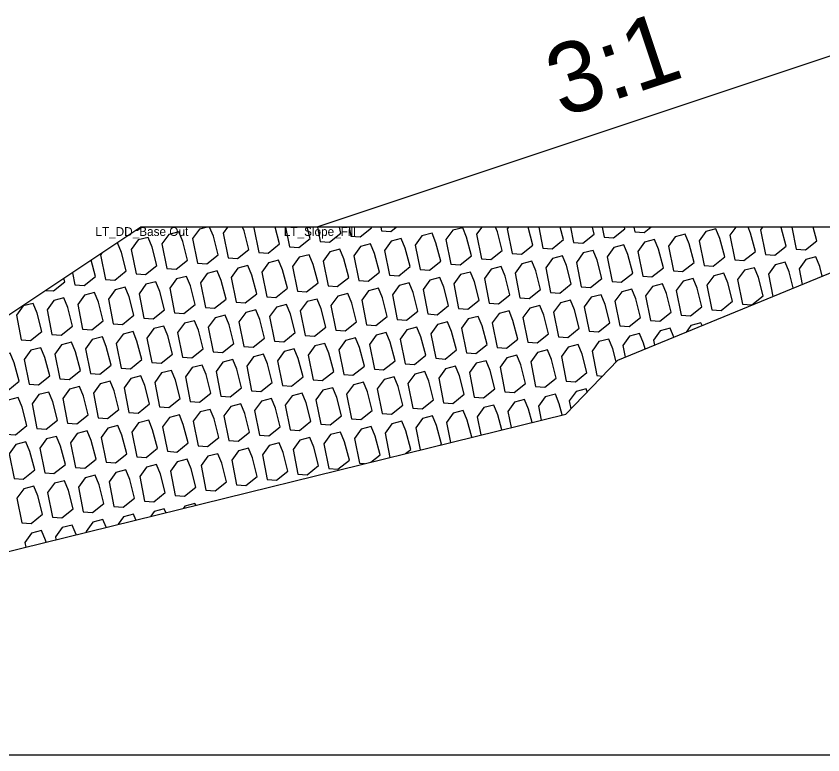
# Model space of a CAD drawing. Extents: x -26 to 203, y -10 to 20020.
# Drawn here: x 69.63 to 78.79, y 3000 to 3008.4 of the extents above; entities that cross this region are included whole.
import ezdxf

# ---------------------------------------------------------------- set-up
doc = ezdxf.new("R2010")
doc.units = 0
for name, color, linetype in [('Default', 7, 'Continuous'), ('Exist Cross Section Cell', 7, 'Continuous'), ('Exist XS Ground Line', 7, 'Continuous'), ('Old_Level_1', 7, 'Continuous'), ('Prop CMT Rip Rap Class II', 7, 'Continuous'), ('Prop CMT Slope Grass', 7, 'Continuous'), ('Prop XS Side Slope Text', 7, 'Continuous')]:
    doc.layers.add(name, color=color, linetype=linetype)

msp = doc.modelspace()

# ---------------------------------------------------------------- linework, layer by layer
at = {"layer": 'Exist Cross Section Cell'}
msp.add_line((0, 3000), (100, 3000), dxfattribs=at)
at = {"layer": 'Exist XS Ground Line'}
for p, q in [((76.4636, 3004.4871), (83.4343, 3007.3577)), ((75.8737, 3003.8749), (76.4636, 3004.4871)), ((69.1249, 3002.2125), (75.8737, 3003.8749))]:
    msp.add_line(p, q, dxfattribs=at)
at = {"layer": 'Old_Level_1'}
for p, q in [((72.69, 3006), (72.7347, 3005.7748)), ((73.0508, 3006), (73.0833, 3005.8363)), ((73.4116, 3006), (73.4319, 3005.8977)), ((73.7724, 3006), (73.7805, 3005.9592)), ((75.5652, 3006), (75.6123, 3005.7625)), ((75.926, 3006), (75.9609, 3005.8239)), ((76.2868, 3006), (76.3095, 3005.8854)), ((76.6476, 3006), (76.6581, 3005.9469)), ((78.4404, 3006), (78.49, 3005.7501)), ((70.2673, 3005.4814), (70.2945, 3005.3445)), ((76.2276, 3004.3117), (76.2903, 3004.3072)), ((73.5277, 3003.3159), (73.5869, 3003.3116))]:
    msp.add_line(p, q, dxfattribs=at)
for points in [[(70.9927, 3005.965), (71.0081, 3005.9639), (71.0534, 3006)], [(71.8, 3006), (71.7104, 3005.9768), (71.6333, 3005.8704), (71.6889, 3005.5904)], [(71.6889, 3005.5904), (71.7942, 3005.5828), (71.9237, 3005.686), (71.8693, 3005.8965), (71.8267, 3006)], [(72.0312, 3006), (71.9819, 3005.9319), (72.0375, 3005.6519)], [(72.0375, 3005.6519), (72.1428, 3005.6442), (72.2723, 3005.7474), (72.2179, 3005.958), (72.2006, 3006)], [(72.3353, 3006), (72.3305, 3005.9933), (72.3861, 3005.7133)], [(72.3861, 3005.7133), (72.4914, 3005.7057), (72.6209, 3005.8089), (72.5715, 3006)], [(72.7347, 3005.7748), (72.84, 3005.7672), (72.9695, 3005.8704), (72.936, 3006)], [(73.0833, 3005.8363), (73.1886, 3005.8286), (73.3181, 3005.9318), (73.3005, 3006)], [(73.4319, 3005.8977), (73.5372, 3005.8901), (73.6667, 3005.9933), (73.665, 3006)], [(73.7805, 3005.9592), (73.8857, 3005.9516), (73.9465, 3006)], [(74.9178, 3006), (74.8595, 3005.9195), (74.9152, 3005.6395)], [(74.9152, 3005.6395), (75.0204, 3005.6319), (75.15, 3005.7351), (75.0955, 3005.9457), (75.0732, 3006)], [(75.2219, 3006), (75.2081, 3005.981), (75.2638, 3005.701)], [(75.2638, 3005.701), (75.369, 3005.6934), (75.4986, 3005.7966), (75.446, 3006)], [(75.6123, 3005.7625), (75.7176, 3005.7548), (75.8472, 3005.858), (75.8104, 3006)], [(75.9609, 3005.8239), (76.0662, 3005.8163), (76.1957, 3005.9195), (76.1749, 3006)], [(76.3095, 3005.8854), (76.4148, 3005.8778), (76.5443, 3005.981), (76.5394, 3006)], [(76.6581, 3005.9469), (76.7634, 3005.9392), (76.8397, 3006)], [(77.4442, 3005.5657), (77.5495, 3005.5581), (77.679, 3005.6613), (77.6246, 3005.8719), (77.5794, 3005.9816), (77.4657, 3005.9522), (77.3886, 3005.8457), (77.4442, 3005.5657)], [(77.8044, 3006), (77.7372, 3005.9072), (77.7928, 3005.6272)], [(77.7928, 3005.6272), (77.8981, 3005.6196), (78.0276, 3005.7228), (77.9732, 3005.9333), (77.9457, 3006)], [(78.1085, 3006), (78.0858, 3005.9687), (78.1414, 3005.6887)], [(78.1414, 3005.6887), (78.2467, 3005.681), (78.3762, 3005.7842), (78.3218, 3005.9948), (78.3196, 3006)], [(78.49, 3005.7501), (78.5953, 3005.7425), (78.7248, 3005.8457), (78.6849, 3006)], [(70.6431, 3005.406), (70.7484, 3005.3984), (70.8779, 3005.5016), (70.8235, 3005.7121), (70.7783, 3005.8218), (70.7777, 3005.8217)], [(73.5208, 3005.3937), (73.626, 3005.386), (73.7556, 3005.4892), (73.7011, 3005.6998), (73.656, 3005.8095), (73.5422, 3005.7801), (73.4652, 3005.6737), (73.5208, 3005.3937)], [(73.8694, 3005.4551), (73.9746, 3005.4475), (74.1042, 3005.5507), (74.0497, 3005.7613), (74.0046, 3005.871), (73.8908, 3005.8416), (73.8138, 3005.7351), (73.8694, 3005.4551)], [(70.2945, 3005.3445), (70.3998, 3005.3369), (70.5293, 3005.4401), (70.4817, 3005.6243)], [(70.5999, 3005.7031), (70.5875, 3005.686), (70.6431, 3005.406)], [(78.7872, 3005.444), (78.7592, 3005.5522), (78.7141, 3005.6619), (78.6003, 3005.6325), (78.5233, 3005.5261), (78.5583, 3005.3497)], [(78.4578, 3005.3083), (78.4106, 3005.4907), (78.3655, 3005.6004), (78.2517, 3005.571), (78.1747, 3005.4646), (78.2248, 3005.2123)], [(74.6554, 3005.074), (74.7607, 3005.0664), (74.8902, 3005.1696), (74.8358, 3005.3801), (74.7907, 3005.4898), (74.6769, 3005.4604), (74.5998, 3005.354), (74.6554, 3005.074)], [(69.9675, 3005.2815), (70.0512, 3005.2754), (70.1807, 3005.3786), (70.1708, 3005.417)], [(74.3068, 3005.0125), (74.4121, 3005.0049), (74.5416, 3005.1081), (74.4872, 3005.3187), (74.4421, 3005.4284), (74.3283, 3005.399), (74.2512, 3005.2925), (74.3068, 3005.0125)], [(76.8359, 3004.9387), (76.9412, 3004.9311), (77.0707, 3005.0343), (77.0163, 3005.2449), (76.9711, 3005.3546), (76.8574, 3005.3252), (76.7803, 3005.2187), (76.8359, 3004.9387)], [(77.1845, 3005.0002), (77.2898, 3004.9926), (77.4193, 3005.0958), (77.3649, 3005.3063), (77.3197, 3005.416), (77.2059, 3005.3866), (77.1289, 3005.2802), (77.1845, 3005.0002)], [(75.7901, 3004.7543), (75.8954, 3004.7467), (76.0249, 3004.8499), (75.9705, 3005.0605), (75.9253, 3005.1702), (75.8116, 3005.1408), (75.7345, 3005.0343), (75.7901, 3004.7543)], [(75.4415, 3004.6929), (75.5468, 3004.6852), (75.6763, 3004.7884), (75.6219, 3004.999), (75.5767, 3005.1087), (75.463, 3005.0793), (75.3859, 3004.9729), (75.4415, 3004.6929)], [(75.0929, 3004.6314), (75.1982, 3004.6238), (75.3277, 3004.727), (75.2733, 3004.9375), (75.2281, 3005.0472), (75.1144, 3005.0178), (75.0373, 3004.9114), (75.0929, 3004.6314)], [(77.4212, 3004.8814), (77.4086, 3004.912), (77.2948, 3004.8826), (77.24, 3004.8068)], [(76.7733, 3004.6146), (76.7565, 3004.6793), (76.7114, 3004.789), (76.5976, 3004.7596), (76.5206, 3004.6532), (76.5468, 3004.5213)], [(77.1015, 3004.7497), (77.06, 3004.8505), (76.9462, 3004.8211), (76.8692, 3004.7147), (76.8803, 3004.6587)], [(76.4464, 3004.4692), (76.4079, 3004.6179), (76.3628, 3004.7276), (76.249, 3004.6982), (76.172, 3004.5917), (76.2276, 3004.3117)], [(75.879, 3004.2503), (75.9843, 3004.2426), (76.1138, 3004.3458), (76.0593, 3004.5564), (76.0142, 3004.6661), (75.9004, 3004.6367), (75.8234, 3004.5303), (75.879, 3004.2503)], [(76.1172, 3004.1276), (76.1031, 3004.162), (75.9893, 3004.1326), (75.9123, 3004.0262), (75.9306, 3003.9339)], [(75.8322, 3003.8647), (75.7996, 3003.9909), (75.7545, 3004.1006), (75.6407, 3004.0711), (75.5637, 3003.9647), (75.5951, 3003.8063)], [(75.1469, 3003.6959), (75.1024, 3003.8679), (75.0573, 3003.9776), (74.9435, 3003.9482), (74.8665, 3003.8418), (74.9072, 3003.6368)], [(75.4896, 3003.7803), (75.451, 3003.9294), (75.4059, 3004.0391), (75.2921, 3004.0097), (75.2151, 3003.9033), (75.2512, 3003.7216)], [(74.8043, 3003.6115), (74.7538, 3003.8065), (74.7087, 3003.9162), (74.5949, 3003.8867), (74.5179, 3003.7803), (74.5632, 3003.5521)], [(74.0526, 3003.4263), (74.1111, 3003.473), (74.0566, 3003.6835), (74.0115, 3003.7932), (73.8977, 3003.7638), (73.8207, 3003.6574), (73.8752, 3003.3826)], [(74.4455, 3003.5231), (74.4597, 3003.5344), (74.4052, 3003.745), (74.3601, 3003.8547), (74.2463, 3003.8253), (74.1693, 3003.7189), (74.2192, 3003.4674)], [(73.6596, 3003.3295), (73.7625, 3003.4115), (73.7081, 3003.6221), (73.6629, 3003.7318), (73.5491, 3003.7023), (73.4721, 3003.5959), (73.5277, 3003.3159)], [(71.3289, 3002.7554), (71.3116, 3002.7974), (71.1979, 3002.768), (71.1583, 3002.7134)], [(71.6684, 3002.839), (71.6602, 3002.8589), (71.5464, 3002.8295), (71.5284, 3002.8046)], [(70.9894, 3002.6718), (70.963, 3002.736), (70.8493, 3002.7065), (70.7882, 3002.6222)], [(70.3105, 3002.5045), (70.2658, 3002.613), (70.1521, 3002.5836), (70.075, 3002.4772), (70.0808, 3002.448)], [(70.6499, 3002.5882), (70.6144, 3002.6745), (70.5007, 3002.6451), (70.4236, 3002.5386), (70.4248, 3002.5327)], [(69.968, 3002.4202), (69.9624, 3002.4419), (69.9172, 3002.5516), (69.8035, 3002.5221), (69.7264, 3002.4157), (69.7368, 3002.3632)]]:
    msp.add_lwpolyline(points, dxfattribs=at)
for points in [[(74.5666, 3005.5781), (74.6718, 3005.5704), (74.8014, 3005.6736), (74.7469, 3005.8842), (74.7018, 3005.9939), (74.588, 3005.9645), (74.5109, 3005.8581)], [(71.3403, 3005.5289), (71.4456, 3005.5213), (71.5751, 3005.6245), (71.5207, 3005.8351), (71.4755, 3005.9448), (71.3618, 3005.9154), (71.2847, 3005.8089)], [(74.218, 3005.5166), (74.3232, 3005.509), (74.4528, 3005.6122), (74.3983, 3005.8227), (74.3532, 3005.9324), (74.2394, 3005.903), (74.1624, 3005.7966)], [(77.0956, 3005.5043), (77.2009, 3005.4966), (77.3304, 3005.5998), (77.276, 3005.8104), (77.2308, 3005.9201), (77.1171, 3005.8907), (77.04, 3005.7843)], [(70.9917, 3005.4675), (71.097, 3005.4598), (71.2265, 3005.563), (71.1721, 3005.7736), (71.1269, 3005.8833), (71.0132, 3005.8539), (70.9361, 3005.7475)], [(76.3984, 3005.3813), (76.5037, 3005.3737), (76.6332, 3005.4769), (76.5788, 3005.6875), (76.5336, 3005.7972), (76.4199, 3005.7678), (76.3428, 3005.6613)], [(76.747, 3005.4428), (76.8523, 3005.4352), (76.9818, 3005.5384), (76.9274, 3005.7489), (76.8822, 3005.8586), (76.7685, 3005.8292), (76.6914, 3005.7228)], [(73.1722, 3005.3322), (73.2774, 3005.3246), (73.407, 3005.4278), (73.3525, 3005.6383), (73.3074, 3005.748), (73.1936, 3005.7186), (73.1166, 3005.6122)], [(76.0498, 3005.3199), (76.1551, 3005.3122), (76.2846, 3005.4154), (76.2302, 3005.626), (76.185, 3005.7357), (76.0713, 3005.7063), (75.9942, 3005.5999)], [(72.475, 3005.2093), (72.5802, 3005.2016), (72.7098, 3005.3048), (72.6553, 3005.5154), (72.6102, 3005.6251), (72.4964, 3005.5957), (72.4194, 3005.4893)], [(72.8236, 3005.2707), (72.9288, 3005.2631), (73.0584, 3005.3663), (73.0039, 3005.5769), (72.9588, 3005.6866), (72.845, 3005.6572), (72.768, 3005.5507)], [(75.7012, 3005.2584), (75.8065, 3005.2508), (75.936, 3005.354), (75.8816, 3005.5645), (75.8364, 3005.6742), (75.7227, 3005.6448), (75.6456, 3005.5384)], [(72.1264, 3005.1478), (72.2316, 3005.1402), (72.3612, 3005.2434), (72.3067, 3005.4539), (72.2616, 3005.5636), (72.1478, 3005.5342), (72.0708, 3005.4278)], [(75.004, 3005.1355), (75.1093, 3005.1278), (75.2388, 3005.231), (75.1844, 3005.4416), (75.1392, 3005.5513), (75.0255, 3005.5219), (74.9484, 3005.4155)], [(75.3526, 3005.1969), (75.4579, 3005.1893), (75.5874, 3005.2925), (75.533, 3005.5031), (75.4878, 3005.6128), (75.3741, 3005.5834), (75.297, 3005.4769)], [(77.8817, 3005.1231), (77.987, 3005.1155), (78.1165, 3005.2187), (78.062, 3005.4293), (78.0169, 3005.539), (77.9031, 3005.5096), (77.8261, 3005.4031)], [(71.4292, 3005.0249), (71.5345, 3005.0172), (71.664, 3005.1204), (71.6095, 3005.331), (71.5644, 3005.4407), (71.4506, 3005.4113), (71.3736, 3005.3049)], [(71.7778, 3005.0863), (71.883, 3005.0787), (72.0126, 3005.1819), (71.9581, 3005.3925), (71.913, 3005.5022), (71.7992, 3005.4728), (71.7222, 3005.3663)], [(77.5331, 3005.0617), (77.6384, 3005.054), (77.7679, 3005.1572), (77.7135, 3005.3678), (77.6683, 3005.4775), (77.5545, 3005.4481), (77.4775, 3005.3417)], [(71.0806, 3004.9634), (71.1859, 3004.9558), (71.3154, 3005.059), (71.2609, 3005.2695), (71.2158, 3005.3792), (71.102, 3005.3498), (71.025, 3005.2434)], [(73.9582, 3004.9511), (74.0635, 3004.9434), (74.193, 3005.0466), (74.1386, 3005.2572), (74.0935, 3005.3669), (73.9797, 3005.3375), (73.9026, 3005.2311)], [(70.3834, 3004.8405), (70.4887, 3004.8328), (70.6182, 3004.936), (70.5638, 3005.1466), (70.5186, 3005.2563), (70.4049, 3005.2269), (70.3278, 3005.1205)], [(70.732, 3004.9019), (70.8373, 3004.8943), (70.9668, 3004.9975), (70.9124, 3005.2081), (70.8672, 3005.3178), (70.7534, 3005.2884), (70.6764, 3005.1819)], [(73.6096, 3004.8896), (73.7149, 3004.882), (73.8445, 3004.9852), (73.79, 3005.1957), (73.7449, 3005.3054), (73.6311, 3005.276), (73.554, 3005.1696)], [(76.4873, 3004.8773), (76.5926, 3004.8696), (76.7221, 3004.9728), (76.6677, 3005.1834), (76.6225, 3005.2931), (76.5088, 3005.2637), (76.4317, 3005.1573)], [(70.0348, 3004.779), (70.1401, 3004.7714), (70.2696, 3004.8746), (70.2152, 3005.0851), (70.17, 3005.1948), (70.0563, 3005.1654), (69.9792, 3005.059)], [(72.9125, 3004.7667), (73.0177, 3004.759), (73.1473, 3004.8622), (73.0928, 3005.0728), (73.0477, 3005.1825), (72.9339, 3005.1531), (72.8568, 3005.0467)], [(73.2611, 3004.8281), (73.3663, 3004.8205), (73.4959, 3004.9237), (73.4414, 3005.1343), (73.3963, 3005.244), (73.2825, 3005.2146), (73.2054, 3005.1081)], [(76.1387, 3004.8158), (76.244, 3004.8082), (76.3735, 3004.9114), (76.3191, 3005.1219), (76.2739, 3005.2316), (76.1602, 3005.2022), (76.0831, 3005.0958)], [(69.6862, 3004.7175), (69.7915, 3004.7099), (69.921, 3004.8131), (69.8666, 3005.0237), (69.8214, 3005.1334), (69.7077, 3005.104), (69.6306, 3004.9975)], [(72.5639, 3004.7052), (72.6691, 3004.6976), (72.7987, 3004.8008), (72.7442, 3005.0113), (72.6991, 3005.121), (72.5853, 3005.0916), (72.5083, 3004.9852)], [(71.8667, 3004.5823), (71.9719, 3004.5746), (72.1015, 3004.6778), (72.047, 3004.8884), (72.0019, 3004.9981), (71.8881, 3004.9687), (71.8111, 3004.8623)], [(72.2153, 3004.6437), (72.3205, 3004.6361), (72.4501, 3004.7393), (72.3956, 3004.9499), (72.3505, 3005.0596), (72.2367, 3005.0302), (72.1597, 3004.9237)], [(74.7443, 3004.5699), (74.8496, 3004.5623), (74.9791, 3004.6655), (74.9247, 3004.8761), (74.8795, 3004.9858), (74.7658, 3004.9564), (74.6887, 3004.8499)], [(71.5181, 3004.5208), (71.6233, 3004.5132), (71.7529, 3004.6164), (71.6984, 3004.8269), (71.6533, 3004.9366), (71.5395, 3004.9072), (71.4625, 3004.8008)], [(74.3957, 3004.5085), (74.501, 3004.5008), (74.6305, 3004.604), (74.5761, 3004.8146), (74.5309, 3004.9243), (74.4172, 3004.8949), (74.3401, 3004.7885)], [(70.8209, 3004.3979), (70.9261, 3004.3902), (71.0557, 3004.4934), (71.0012, 3004.704), (70.9561, 3004.8137), (70.8423, 3004.7843), (70.7653, 3004.6779)], [(71.1695, 3004.4593), (71.2747, 3004.4517), (71.4043, 3004.5549), (71.3498, 3004.7655), (71.3047, 3004.8752), (71.1909, 3004.8458), (71.1139, 3004.7393)], [(73.6985, 3004.3855), (73.8038, 3004.3779), (73.9333, 3004.4811), (73.8789, 3004.6917), (73.8337, 3004.8014), (73.72, 3004.772), (73.6429, 3004.6655)], [(74.0471, 3004.447), (74.1524, 3004.4394), (74.2819, 3004.5426), (74.2275, 3004.7531), (74.1823, 3004.8628), (74.0686, 3004.8334), (73.9915, 3004.727)], [(70.4723, 3004.3364), (70.5775, 3004.3288), (70.7071, 3004.432), (70.6526, 3004.6425), (70.6075, 3004.7522), (70.4937, 3004.7228), (70.4167, 3004.6164)], [(73.3499, 3004.3241), (73.4552, 3004.3164), (73.5847, 3004.4196), (73.5303, 3004.6302), (73.4851, 3004.7399), (73.3714, 3004.7105), (73.2943, 3004.6041)], [(69.7751, 3004.2135), (69.8804, 3004.2058), (70.0099, 3004.309), (69.9554, 3004.5196), (69.9103, 3004.6293), (69.7965, 3004.5999), (69.7195, 3004.4935)], [(70.1237, 3004.2749), (70.2289, 3004.2673), (70.3585, 3004.3705), (70.304, 3004.5811), (70.2589, 3004.6908), (70.1451, 3004.6614), (70.0681, 3004.5549)], [(72.6527, 3004.2011), (72.758, 3004.1935), (72.8875, 3004.2967), (72.8331, 3004.5073), (72.788, 3004.617), (72.6742, 3004.5876), (72.5971, 3004.4811)], [(73.0013, 3004.2626), (73.1066, 3004.255), (73.2361, 3004.3582), (73.1817, 3004.5687), (73.1365, 3004.6784), (73.0228, 3004.649), (72.9457, 3004.5426)], [(69.4265, 3004.152), (69.5318, 3004.1444), (69.6613, 3004.2476), (69.6068, 3004.4581), (69.5617, 3004.5678), (69.4479, 3004.5384), (69.3709, 3004.432)], [(72.3041, 3004.1397), (72.4094, 3004.132), (72.5389, 3004.2352), (72.4845, 3004.4458), (72.4394, 3004.5555), (72.3256, 3004.5261), (72.2485, 3004.4197)], [(75.1818, 3004.1273), (75.2871, 3004.1197), (75.4166, 3004.2229), (75.3622, 3004.4335), (75.317, 3004.5432), (75.2033, 3004.5138), (75.1262, 3004.4073)], [(75.5304, 3004.1888), (75.6357, 3004.1812), (75.7652, 3004.2844), (75.7108, 3004.4949), (75.6656, 3004.6046), (75.5518, 3004.5752), (75.4748, 3004.4688)], [(71.607, 3004.0167), (71.7122, 3004.0091), (71.8418, 3004.1123), (71.7873, 3004.3229), (71.7422, 3004.4326), (71.6284, 3004.4031), (71.5513, 3004.2967)], [(71.9555, 3004.0782), (72.0608, 3004.0706), (72.1903, 3004.1738), (72.1359, 3004.3843), (72.0908, 3004.494), (71.977, 3004.4646), (71.8999, 3004.3582)], [(74.8332, 3004.0659), (74.9385, 3004.0582), (75.068, 3004.1614), (75.0136, 3004.372), (74.9684, 3004.4817), (74.8547, 3004.4523), (74.7776, 3004.3459)], [(71.2584, 3003.9553), (71.3636, 3003.9476), (71.4932, 3004.0508), (71.4387, 3004.2614), (71.3936, 3004.3711), (71.2798, 3004.3417), (71.2027, 3004.2353)], [(74.136, 3003.9429), (74.2413, 3003.9353), (74.3708, 3004.0385), (74.3164, 3004.2491), (74.2712, 3004.3588), (74.1575, 3004.3293), (74.0804, 3004.2229)], [(74.4846, 3004.0044), (74.5899, 3003.9968), (74.7194, 3004.1), (74.665, 3004.3105), (74.6198, 3004.4202), (74.5061, 3004.3908), (74.429, 3004.2844)], [(70.5612, 3003.8323), (70.6664, 3003.8247), (70.796, 3003.9279), (70.7415, 3004.1385), (70.6964, 3004.2482), (70.5826, 3004.2187), (70.5056, 3004.1123)], [(70.9098, 3003.8938), (71.015, 3003.8861), (71.1446, 3003.9894), (71.0901, 3004.1999), (71.045, 3004.3096), (70.9312, 3004.2802), (70.8541, 3004.1738)], [(73.7874, 3003.8815), (73.8927, 3003.8738), (74.0222, 3003.977), (73.9678, 3004.1876), (73.9226, 3004.2973), (73.8089, 3004.2679), (73.7318, 3004.1615)], [(70.2126, 3003.7709), (70.3178, 3003.7632), (70.4474, 3003.8664), (70.3929, 3004.077), (70.3478, 3004.1867), (70.234, 3004.1573), (70.157, 3004.0509)], [(73.0902, 3003.7585), (73.1955, 3003.7509), (73.325, 3003.8541), (73.2706, 3004.0647), (73.2254, 3004.1744), (73.1117, 3004.1449), (73.0346, 3004.0385)], [(73.4388, 3003.82), (73.5441, 3003.8123), (73.6736, 3003.9156), (73.6192, 3004.1261), (73.574, 3004.2358), (73.4603, 3004.2064), (73.3832, 3004.1)], [(69.5154, 3003.6479), (69.6206, 3003.6403), (69.7502, 3003.7435), (69.6957, 3003.9541), (69.6506, 3004.0638), (69.5368, 3004.0343), (69.4598, 3003.9279)], [(69.864, 3003.7094), (69.9692, 3003.7017), (70.0988, 3003.805), (70.0443, 3004.0155), (69.9992, 3004.1252), (69.8854, 3004.0958), (69.8084, 3003.9894)], [(72.7416, 3003.6971), (72.8469, 3003.6894), (72.9764, 3003.7926), (72.922, 3004.0032), (72.8768, 3004.1129), (72.7631, 3004.0835), (72.686, 3003.9771)], [(72.0444, 3003.5741), (72.1497, 3003.5665), (72.2792, 3003.6697), (72.2248, 3003.8803), (72.1796, 3003.99), (72.0659, 3003.9605), (71.9888, 3003.8541)], [(72.393, 3003.6356), (72.4983, 3003.6279), (72.6278, 3003.7312), (72.5734, 3003.9417), (72.5282, 3004.0514), (72.4145, 3004.022), (72.3374, 3003.9156)], [(71.6958, 3003.5127), (71.8011, 3003.505), (71.9306, 3003.6082), (71.8762, 3003.8188), (71.831, 3003.9285), (71.7173, 3003.8991), (71.6402, 3003.7927)], [(70.9986, 3003.3897), (71.1039, 3003.3821), (71.2334, 3003.4853), (71.179, 3003.6959), (71.1339, 3003.8056), (71.0201, 3003.7761), (70.943, 3003.6697)], [(71.3472, 3003.4512), (71.4525, 3003.4435), (71.582, 3003.5468), (71.5276, 3003.7573), (71.4824, 3003.867), (71.3687, 3003.8376), (71.2916, 3003.7312)], [(70.65, 3003.3283), (70.7553, 3003.3206), (70.8848, 3003.4238), (70.8304, 3003.6344), (70.7853, 3003.7441), (70.6715, 3003.7147), (70.5944, 3003.6083)], [(69.9528, 3003.2053), (70.0581, 3003.1977), (70.1877, 3003.3009), (70.1332, 3003.5115), (70.0881, 3003.6212), (69.9743, 3003.5917), (69.8972, 3003.4853)], [(70.3014, 3003.2668), (70.4067, 3003.2591), (70.5362, 3003.3624), (70.4818, 3003.5729), (70.4367, 3003.6826), (70.3229, 3003.6532), (70.2458, 3003.5468)], [(72.8305, 3003.193), (72.9358, 3003.1853), (73.0653, 3003.2886), (73.0109, 3003.4991), (72.9657, 3003.6088), (72.852, 3003.5794), (72.7749, 3003.473)], [(73.1791, 3003.2545), (73.2844, 3003.2468), (73.4139, 3003.35), (73.3595, 3003.5606), (73.3143, 3003.6703), (73.2006, 3003.6409), (73.1235, 3003.5345)], [(69.6043, 3003.1439), (69.7095, 3003.1362), (69.8391, 3003.2394), (69.7846, 3003.45), (69.7395, 3003.5597), (69.6257, 3003.5303), (69.5486, 3003.4239)], [(72.4819, 3003.1315), (72.5872, 3003.1239), (72.7167, 3003.2271), (72.6623, 3003.4377), (72.6171, 3003.5474), (72.5034, 3003.5179), (72.4263, 3003.4115)], [(71.7847, 3003.0086), (71.89, 3003.0009), (72.0195, 3003.1042), (71.9651, 3003.3147), (71.9199, 3003.4244), (71.8062, 3003.395), (71.7291, 3003.2886)], [(72.1333, 3003.0701), (72.2386, 3003.0624), (72.3681, 3003.1656), (72.3137, 3003.3762), (72.2685, 3003.4859), (72.1548, 3003.4565), (72.0777, 3003.3501)], [(71.4361, 3002.9471), (71.5414, 3002.9395), (71.6709, 3003.0427), (71.6165, 3003.2533), (71.5713, 3003.363), (71.4576, 3003.3335), (71.3805, 3003.2271)], [(70.7389, 3002.8242), (70.8442, 3002.8165), (70.9737, 3002.9198), (70.9193, 3003.1303), (70.8741, 3003.24), (70.7604, 3003.2106), (70.6833, 3003.1042)], [(71.0875, 3002.8857), (71.1928, 3002.878), (71.3223, 3002.9812), (71.2679, 3003.1918), (71.2227, 3003.3015), (71.109, 3003.2721), (71.0319, 3003.1656)], [(70.3903, 3002.7627), (70.4956, 3002.7551), (70.6251, 3002.8583), (70.5707, 3003.0689), (70.5255, 3003.1786), (70.4118, 3003.1491), (70.3347, 3003.0427)], [(69.6931, 3002.6398), (69.7984, 3002.6321), (69.9279, 3002.7354), (69.8735, 3002.9459), (69.8283, 3003.0556), (69.7146, 3003.0262), (69.6375, 3002.9198)], [(70.0417, 3002.7013), (70.147, 3002.6936), (70.2765, 3002.7968), (70.2221, 3003.0074), (70.1769, 3003.1171), (70.0632, 3003.0877), (69.9861, 3002.9812)]]:
    msp.add_lwpolyline(points, close=True, dxfattribs=at)
at = {"layer": 'Prop CMT Rip Rap Class II'}
msp.add_lwpolyline([(80.1375, 3006), (71.0452, 3006), (64.9158, 3001.9135)], dxfattribs=at)
at = {"layer": 'Prop CMT Slope Grass'}
msp.add_lwpolyline([(80, 3008.318), (73.0452, 3006)], dxfattribs=at)

# ---------------------------------------------------------------- texts
at = {"layer": 'Default'}
for s, p in [('LT_DD_Base Out', (70.5286, 3005.9)), ('LT_Slope_Fill', (72.669, 3005.9))]:
    msp.add_text(s, height=0.1, dxfattribs=at).set_placement(p)
at = {"layer": 'Prop XS Side Slope Text'}
msp.add_text('3:1', height=0.8, rotation=18.43323, dxfattribs=at).set_placement((75.8262, 3007.2431))

doc.saveas('drawing.dxf')
